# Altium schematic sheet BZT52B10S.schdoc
size 127 x 101 mm
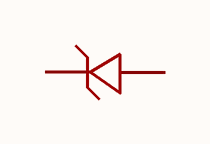
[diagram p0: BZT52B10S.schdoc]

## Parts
D?  bzt52b10s_c78857  [SOD-323_L1.8-W1.3-LS2.5-RD]  (value not drawn)

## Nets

Not connected (* = marked no-connect by the designer): D? 1(C) 2(A)

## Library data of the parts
D? = bzt52b10s_c78857: 二极管配置:1个独立式;稳压值(标称值):10V;稳压值(范围值):9.8V~10.2V;耗散功率(Pd):200mW;; Manufacturer: CJ(江苏长电/长晶); AddInBom: yes; ModelId: db63db13d9e342eb939127d413d6200b; ModelTransform: 104.3305,51.181,0,0,0,0,0,-0.004,0; Diode Configuration: 1个独立式; Zener Voltage(Nom): 10V; Reverse Leakage Current (Ir): 200nA; Pd - Power Dissipation: 200mW; Impedance(Zzt): 20Ω; Impedance(Zzk): 150Ω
